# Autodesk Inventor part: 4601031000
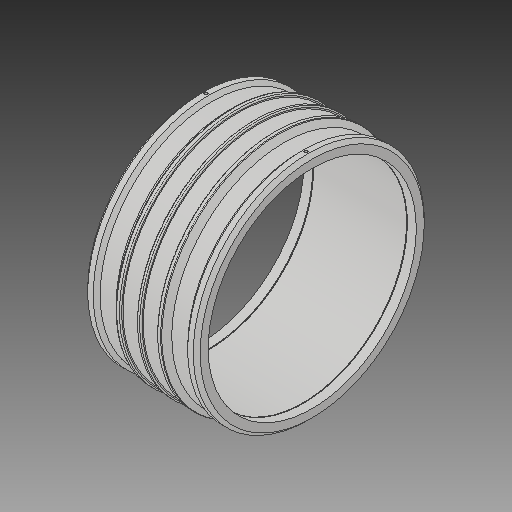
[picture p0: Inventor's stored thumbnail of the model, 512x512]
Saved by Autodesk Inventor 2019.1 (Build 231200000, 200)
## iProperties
Created: 2017-06
Part Number: 4601031000
Material: Generic
Description: PLASSON LIGHTFIT COUPLER 1000
Document SubType Name: Modeling
Designer: KIM
Mass: 17859.4 g
Surface Area: 15499.5 cm^2
Volume: 17859.4 cm^3
Density: 1 g/cm^3
Appearance: Default
Author: KIM
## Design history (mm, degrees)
derived "460103.ipt"
feature "Solid1::460103.ipt"
tag "TaggingFeature1"
body "Solid1"
other parameters: "d14" = 17.6296, "d19" = 3.52592, "d20" = 168 deg, "d23" = 1128, "d24" = 1076.7, "d25" = 135 deg, "d26" = 216, "d27" = 135 deg, "d29" = 555, "d35" = 15, "d39" = 0, "d40" = 4, "d41" = 14, "d42" = 0, "d43" = 135 deg, "d44" = 59.4, "d45" = 21.6, "d46" = 21.6, "d47" = 21.6, "d48" = 1105.44, "d49" = 1128, "d50" = 5.64, "d51" = 6, "d52" = 0, "D_" = 1128, "A_" = 555, "d_2" = 12
